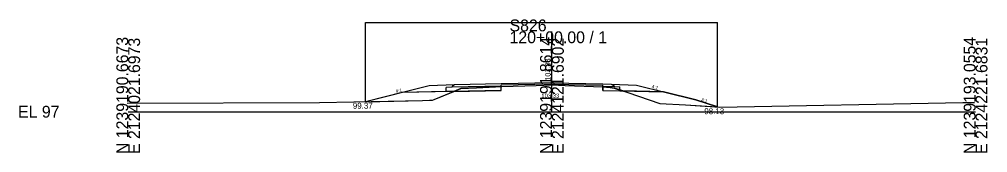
# Model space of a CAD drawing. Extents: x 2119282 to 2119710, y 1215030 to 1220057.
# Drawn here: x 2119381.9 to 2119610.4, y 1218530.1 to 1218561.7 of the extents above; entities that cross this region are included whole.
import ezdxf

# ---------------------------------------------------------------- set-up
doc = ezdxf.new("R2010")
doc.units = 0
for name, color, linetype in [('XS_CELL', 7, 'Continuous'), ('XS_M_DITCH', 7, 'Continuous'), ('XS_M_SHAPES_EARTHWORK', 7, 'Continuous'), ('XS_P_FINISHED_GRADE', 7, 'Continuous'), ('XS_P_FINISHED_GRADE_ELEV_TX', 7, 'Continuous'), ('XS_P_SUBGRADE_GRANULAR', 7, 'Continuous'), ('XS_P_SUBGRADE_PAVEMENT', 7, 'Continuous'), ('XS_P_TX_DCH', 7, 'Continuous'), ('XS_P_TX_FS_BS', 7, 'Continuous'), ('XS_X_GROUND', 7, 'Continuous'), ('XS_X_GROUND_TX', 7, 'Continuous')]:
    doc.layers.add(name, color=color, linetype=linetype)

msp = doc.modelspace()

# ---------------------------------------------------------------- linework, layer by layer
at = {"layer": 'XS_CELL'}
for p, q in [((2119507.6, 1218539.8), (2119507.6, 1218558.81)), ((2119407.6, 1218539.8), (2119507.6, 1218539.8)), ((2119507.6, 1218539.8), (2119607.6, 1218539.8))]:
    msp.add_line(p, q, dxfattribs=at)
at = {"layer": 'XS_M_DITCH'}
for p, q in [((2119463.57, 1218542.17), (2119463.57, 1218560.92)), ((2119463.57, 1218560.92), (2119546.66, 1218560.92)), ((2119546.66, 1218540.93), (2119546.66, 1218560.92))]:
    msp.add_line(p, q, dxfattribs=at)
at = {"layer": 'XS_M_SHAPES_EARTHWORK'}
for p, q in [((2119486.11, 1218545.27), (2119484.44, 1218544.59)), ((2119489.79, 1218545.44), (2119486.11, 1218545.27)), ((2119495.6, 1218545.72), (2119489.79, 1218545.44)), ((2119495.6, 1218544.81), (2119495.6, 1218545.72)), ((2119521.37, 1218545.5), (2119519.6, 1218545.65)), ((2119519.6, 1218545.65), (2119519.6, 1218544.81)), ((2119522.31, 1218545.37), (2119521.37, 1218545.5)), ((2119523.6, 1218544.95), (2119522.31, 1218545.37)), ((2119472.26, 1218544.34), (2119463.57, 1218542.17)), ((2119479.8, 1218542.67), (2119484.44, 1218544.59)), ((2119484.44, 1218544.59), (2119483.97, 1218544.58)), ((2119484.44, 1218544.59), (2119495.6, 1218544.81)), ((2119519.6, 1218544.81), (2119523.6, 1218544.73)), ((2119523.6, 1218544.73), (2119523.6, 1218544.95)), ((2119524.35, 1218544.71), (2119523.6, 1218544.95)), ((2119523.6, 1218544.95), (2119523.6, 1218544.73)), ((2119523.6, 1218544.73), (2119524.35, 1218544.71)), ((2119533.97, 1218544.52), (2119524.35, 1218544.71)), ((2119524.35, 1218544.71), (2119525.52, 1218544.34)), ((2119525.52, 1218544.34), (2119533.05, 1218541.78)), ((2119541.6, 1218542.61), (2119533.97, 1218544.52)), ((2119463.57, 1218542.17), (2119477.04, 1218542.46)), ((2119477.04, 1218542.46), (2119478.68, 1218542.55)), ((2119478.68, 1218542.55), (2119479.41, 1218542.53)), ((2119479.41, 1218542.53), (2119479.8, 1218542.67)), ((2119533.05, 1218541.78), (2119539.15, 1218541.44)), ((2119539.15, 1218541.44), (2119546.66, 1218540.93)), ((2119546.66, 1218540.93), (2119541.6, 1218542.61))]:
    msp.add_line(p, q, dxfattribs=at)
msp.add_lwpolyline([(2119483.97, 1218544.58), (2119482.62, 1218544.55), (2119472.26, 1218544.34)], dxfattribs=at)
at = {"layer": 'XS_P_FINISHED_GRADE'}
for p, q in [((2119478.62, 1218545.93), (2119463.57, 1218542.17)), ((2119484.62, 1218546.17), (2119478.62, 1218545.93)), ((2119495.6, 1218546.39), (2119484.62, 1218546.17)), ((2119507.6, 1218546.63), (2119495.6, 1218546.39)), ((2119507.6, 1218546.63), (2119519.6, 1218546.39)), ((2119519.6, 1218546.39), (2119521.6, 1218546.35)), ((2119521.6, 1218546.35), (2119527.6, 1218546.11)), ((2119527.6, 1218546.11), (2119541.6, 1218542.61)), ((2119541.6, 1218542.61), (2119546.66, 1218540.93))]:
    msp.add_line(p, q, dxfattribs=at)
at = {"layer": 'XS_P_SUBGRADE_GRANULAR'}
for p, q in [((2119483.97, 1218545.58), (2119482.62, 1218545.52)), ((2119482.62, 1218544.55), (2119482.62, 1218545.52)), ((2119495.6, 1218544.81), (2119495.61, 1218545.81)), ((2119519.6, 1218544.81), (2119519.59, 1218545.81)), ((2119522.26, 1218545.76), (2119523.6, 1218545.7)), ((2119523.6, 1218544.73), (2119523.6, 1218545.7)), ((2119483.97, 1218544.58), (2119472.26, 1218544.34)), ((2119495.6, 1218544.81), (2119483.97, 1218544.58)), ((2119519.6, 1218544.81), (2119523.6, 1218544.73)), ((2119523.6, 1218544.73), (2119533.97, 1218544.52))]:
    msp.add_line(p, q, dxfattribs=at)
at = {"layer": 'XS_P_SUBGRADE_PAVEMENT'}
for p, q in [((2119484.12, 1218545.83), (2119483.97, 1218545.58)), ((2119495.61, 1218545.81), (2119483.97, 1218545.58)), ((2119484.62, 1218546.17), (2119484.12, 1218545.83)), ((2119507.6, 1218546.3), (2119495.61, 1218546.06)), ((2119495.61, 1218545.81), (2119495.61, 1218546.06)), ((2119507.6, 1218546.3), (2119519.6, 1218546.06)), ((2119519.59, 1218545.81), (2119519.6, 1218546.06)), ((2119519.59, 1218545.81), (2119522.26, 1218545.76)), ((2119521.6, 1218546.35), (2119522.11, 1218546.01)), ((2119522.11, 1218546.01), (2119522.26, 1218545.76))]:
    msp.add_line(p, q, dxfattribs=at)
at = {"layer": 'XS_X_GROUND'}
for p, q in [((2119479.8, 1218542.67), (2119486.11, 1218545.27)), ((2119486.11, 1218545.27), (2119489.79, 1218545.44)), ((2119489.79, 1218545.44), (2119495.81, 1218545.73)), ((2119495.81, 1218545.73), (2119503.91, 1218546.01)), ((2119503.91, 1218546.01), (2119507.6, 1218546.13)), ((2119507.6, 1218546.13), (2119510.75, 1218545.98)), ((2119510.75, 1218545.98), (2119519.6, 1218545.65)), ((2119519.6, 1218545.65), (2119521.37, 1218545.5)), ((2119521.37, 1218545.5), (2119522.31, 1218545.37)), ((2119522.31, 1218545.37), (2119525.52, 1218544.34)), ((2119525.52, 1218544.34), (2119533.05, 1218541.78)), ((2119407.33, 1218541.85), (2119452.73, 1218541.94)), ((2119452.73, 1218541.94), (2119477.04, 1218542.46)), ((2119477.04, 1218542.46), (2119478.68, 1218542.55)), ((2119478.68, 1218542.55), (2119479.41, 1218542.53)), ((2119479.41, 1218542.53), (2119479.8, 1218542.67)), ((2119533.05, 1218541.78), (2119539.15, 1218541.44)), ((2119539.15, 1218541.44), (2119547.24, 1218540.89)), ((2119547.24, 1218540.89), (2119604.59, 1218541.95)), ((2119604.59, 1218541.95), (2119607.33, 1218542.01))]:
    msp.add_line(p, q, dxfattribs=at)

# ---------------------------------------------------------------- texts
at = {"layer": 'XS_CELL'}
for s, p in [('S826', (2119497.6, 1218558.81)), ('120+00.00 / 1', (2119497.6, 1218556.01)), ('EL 97', (2119381.6, 1218538.4))]:
    msp.add_text(s, height=2.8, dxfattribs=at).set_placement(p)
for s, p in [('N 1239190.6673', (2119407.6, 1218529.8)), ('E 2124021.6973', (2119410.4, 1218529.8)), ('N 1239191.8614', (2119507.6, 1218529.8)), ('E 2124121.6902', (2119510.4, 1218529.8)), ('N 1239193.0554', (2119607.6, 1218529.8)), ('E 2124221.6831', (2119610.4, 1218529.8))]:
    msp.add_text(s, height=2.8, rotation=90, dxfattribs=at).set_placement(p)
at = {"layer": 'XS_P_FINISHED_GRADE_ELEV_TX'}
msp.add_text('103.83', height=1.25, rotation=90, dxfattribs=at).set_placement((2119507.26, 1218547.13))
at = {"layer": 'XS_P_TX_DCH'}
for s, p in [('99.37', (2119460.62, 1218540.51)), ('98.13', (2119543.58, 1218539.22))]:
    msp.add_text(s, height=1.4, dxfattribs=at).set_placement(p)
at = {"layer": 'XS_P_TX_FS_BS'}
for s, rotation, p in [('4:1', 14.0362, (2119470.81, 1218544.2)), ('4:1', 345.9638, (2119531.11, 1218545.41)), ('3:1', 341.5651, (2119542.71, 1218542.39))]:
    msp.add_text(s, height=0.8, rotation=rotation, dxfattribs=at).set_placement(p)
at = {"layer": 'XS_X_GROUND_TX'}
msp.add_text('103.33', height=1, dxfattribs=at).set_placement((2119505.11, 1218543.08))

doc.saveas('drawing.dxf')
